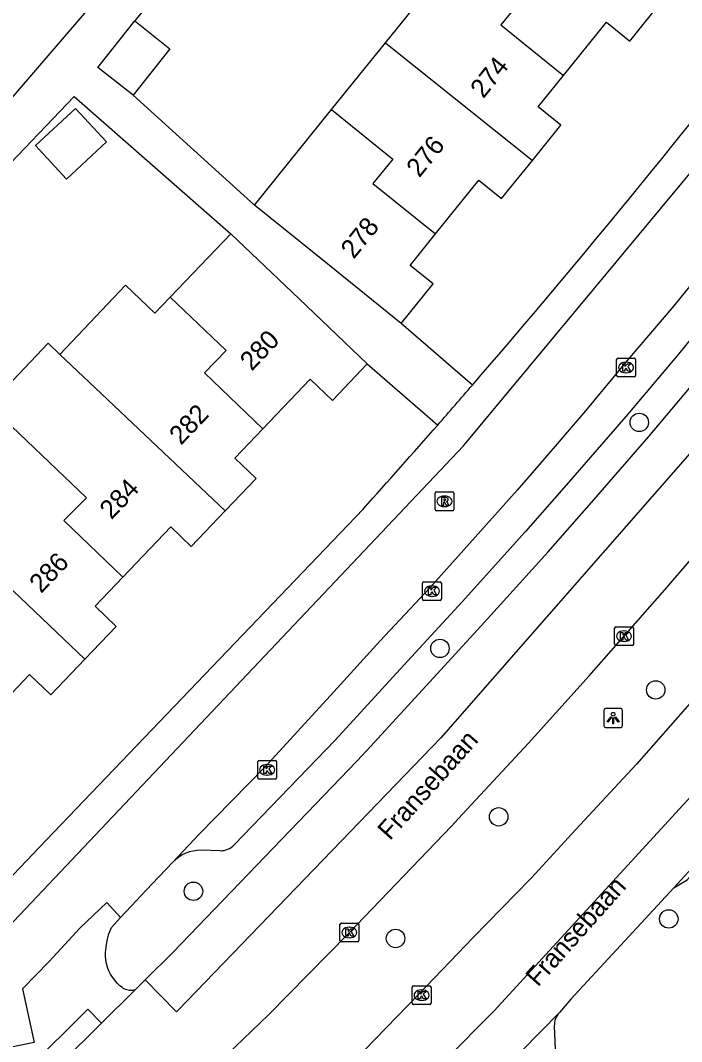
# Model space of a CAD drawing. Extents: x 158474 to 159560, y 388525 to 389605.
# Drawn here: x 158643.2 to 158678.3, y 388854.8 to 388909 of the extents above; entities that cross this region are included whole.
import ezdxf

# ---------------------------------------------------------------- set-up
doc = ezdxf.new("R2010")
doc.units = 0
for name, color, linetype in [('IMGEO_Boom', 7, 'Continuous'), ('IMGEO_Kolk', 7, 'Continuous'), ('IMGEO_Lichtpunt', 7, 'Continuous'), ('IMGEO_Openbare_ruimte_label', 7, 'Continuous'), ('IMGEO_Pand', 7, 'Continuous'), ('IMGEO_Pand_nummerreeks', 7, 'Continuous'), ('IMGEO_Parkeervlak_open', 7, 'Continuous'), ('IMGEO_Rijbaan_lokaal_gesloten', 7, 'Continuous'), ('IMGEO_Rijbaan_lokaal_open', 7, 'Continuous'), ('IMGEO_Rioolput', 7, 'Continuous'), ('IMGEO_Voetpad_open', 7, 'Continuous')]:
    doc.layers.add(name, color=color, linetype=linetype)

msp = doc.modelspace()

# ---------------------------------------------------------------- linework, layer by layer
at = {"layer": 'IMGEO_Boom'}
for centre in [(158676.07, 388887.651), (158665.49, 388875.653), (158676.946, 388873.453), (158668.608, 388866.715), (158652.407, 388862.762), (158677.641, 388861.294), (158663.133, 388860.257)]:
    msp.add_circle(centre, 0.489, dxfattribs=at)
at = {"layer": 'IMGEO_Kolk'}
for p, q in [((158674.871, 388890.139), (158674.871, 388890.991)), ((158674.946, 388891.065), (158675.798, 388891.065)), ((158675.359, 388890.845), (158675.384, 388890.845)), ((158675.872, 388890.991), (158675.872, 388890.139)), ((158675.382, 388890.285), (158675.357, 388890.285)), ((158675.798, 388890.065), (158674.946, 388890.065)), ((158664.568, 388878.271), (158664.568, 388879.123)), ((158664.643, 388879.197), (158665.495, 388879.197)), ((158665.056, 388878.977), (158665.081, 388878.977)), ((158665.569, 388879.123), (158665.569, 388878.271)), ((158665.079, 388878.417), (158665.054, 388878.417)), ((158665.495, 388878.197), (158664.643, 388878.197)), ((158674.762, 388875.875), (158674.762, 388876.727)), ((158674.837, 388876.801), (158675.689, 388876.801)), ((158675.763, 388876.727), (158675.763, 388875.875)), ((158675.25, 388876.581), (158675.275, 388876.581)), ((158675.689, 388875.801), (158674.837, 388875.801)), ((158675.273, 388876.021), (158675.248, 388876.021)), ((158655.819, 388868.783), (158655.819, 388869.635)), ((158655.894, 388869.709), (158656.746, 388869.709)), ((158656.82, 388869.635), (158656.82, 388868.783)), ((158656.307, 388869.489), (158656.332, 388869.489)), ((158656.746, 388868.709), (158655.894, 388868.709)), ((158656.33, 388868.929), (158656.305, 388868.929)), ((158660.181, 388860.15), (158660.181, 388861.002)), ((158660.256, 388861.076), (158661.108, 388861.076)), ((158661.182, 388861.002), (158661.182, 388860.15)), ((158660.669, 388860.856), (158660.694, 388860.856)), ((158661.108, 388860.076), (158660.256, 388860.076)), ((158660.692, 388860.296), (158660.667, 388860.296)), ((158664.016, 388856.825), (158664.016, 388857.677)), ((158664.091, 388857.751), (158664.943, 388857.751)), ((158665.017, 388857.677), (158665.017, 388856.825)), ((158664.504, 388857.531), (158664.529, 388857.531)), ((158664.943, 388856.751), (158664.091, 388856.751)), ((158664.527, 388856.971), (158664.502, 388856.971))]:
    msp.add_line(p, q, dxfattribs=at)
for points in [[(158674.871, 388890.139), (158674.871, 388890.991)], [(158674.946, 388891.065), (158675.798, 388891.065)], [(158675.192, 388890.765), (158675.315, 388890.765), (158675.315, 388890.614), (158675.445, 388890.765), (158675.609, 388890.765), (158675.463, 388890.614), (158675.616, 388890.365), (158675.464, 388890.365), (158675.379, 388890.529), (158675.315, 388890.462), (158675.315, 388890.365), (158675.192, 388890.365), (158675.192, 388890.765)], [(158675.872, 388890.991), (158675.872, 388890.139)], [(158675.798, 388890.065), (158674.946, 388890.065)], [(158664.568, 388878.271), (158664.568, 388879.123)], [(158664.643, 388879.197), (158665.495, 388879.197)], [(158664.889, 388878.897), (158665.012, 388878.897), (158665.012, 388878.746), (158665.142, 388878.897), (158665.306, 388878.897), (158665.16, 388878.746), (158665.313, 388878.497), (158665.161, 388878.497), (158665.076, 388878.661), (158665.012, 388878.594), (158665.012, 388878.497), (158664.889, 388878.497), (158664.889, 388878.897)], [(158665.569, 388879.123), (158665.569, 388878.271)], [(158665.495, 388878.197), (158664.643, 388878.197)], [(158674.762, 388875.875), (158674.762, 388876.727)], [(158674.837, 388876.801), (158675.689, 388876.801)], [(158675.763, 388876.727), (158675.763, 388875.875)], [(158675.083, 388876.501), (158675.206, 388876.501), (158675.206, 388876.35), (158675.336, 388876.501), (158675.5, 388876.501), (158675.354, 388876.35), (158675.507, 388876.101), (158675.355, 388876.101), (158675.27, 388876.265), (158675.206, 388876.198), (158675.206, 388876.101), (158675.083, 388876.101), (158675.083, 388876.501)], [(158675.689, 388875.801), (158674.837, 388875.801)], [(158655.819, 388868.783), (158655.819, 388869.635)], [(158655.894, 388869.709), (158656.746, 388869.709)], [(158656.82, 388869.635), (158656.82, 388868.783)], [(158656.14, 388869.409), (158656.263, 388869.409), (158656.263, 388869.258), (158656.393, 388869.409), (158656.557, 388869.409), (158656.411, 388869.258), (158656.564, 388869.009), (158656.412, 388869.009), (158656.327, 388869.173), (158656.263, 388869.106), (158656.263, 388869.009), (158656.14, 388869.009), (158656.14, 388869.409)], [(158656.746, 388868.709), (158655.894, 388868.709)], [(158660.181, 388860.15), (158660.181, 388861.002)], [(158660.256, 388861.076), (158661.108, 388861.076)], [(158661.182, 388861.002), (158661.182, 388860.15)], [(158660.502, 388860.776), (158660.625, 388860.776), (158660.625, 388860.625), (158660.755, 388860.776), (158660.919, 388860.776), (158660.773, 388860.625), (158660.926, 388860.376), (158660.774, 388860.376), (158660.689, 388860.54), (158660.625, 388860.473), (158660.625, 388860.376), (158660.502, 388860.376), (158660.502, 388860.776)], [(158661.108, 388860.076), (158660.256, 388860.076)], [(158664.016, 388856.825), (158664.016, 388857.677)], [(158664.091, 388857.751), (158664.943, 388857.751)], [(158665.017, 388857.677), (158665.017, 388856.825)], [(158664.337, 388857.451), (158664.46, 388857.451), (158664.46, 388857.3), (158664.59, 388857.451), (158664.754, 388857.451), (158664.608, 388857.3), (158664.761, 388857.051), (158664.609, 388857.051), (158664.524, 388857.215), (158664.46, 388857.148), (158664.46, 388857.051), (158664.337, 388857.051), (158664.337, 388857.451)], [(158664.943, 388856.751), (158664.091, 388856.751)]]:
    msp.add_lwpolyline(points, dxfattribs=at)
for centre, start, end in [((158674.948, 388890.989), 91.552, 178.448), ((158674.948, 388890.989), 91.552, 178.448), ((158675.796, 388890.989), 1.552, 88.448), ((158675.796, 388890.989), 1.552, 88.448), ((158674.948, 388890.141), 181.552, 268.448), ((158674.948, 388890.141), 181.552, 268.448), ((158675.796, 388890.141), 271.552, 358.448), ((158675.796, 388890.141), 271.552, 358.448), ((158664.645, 388879.121), 91.552, 178.448), ((158664.645, 388879.121), 91.552, 178.448), ((158665.493, 388879.121), 1.552, 88.448), ((158665.493, 388879.121), 1.552, 88.448), ((158664.645, 388878.273), 181.552, 268.448), ((158664.645, 388878.273), 181.552, 268.448), ((158665.493, 388878.273), 271.552, 358.448), ((158665.493, 388878.273), 271.552, 358.448), ((158674.839, 388876.725), 91.552, 178.448), ((158674.839, 388876.725), 91.552, 178.448), ((158675.687, 388876.725), 1.552, 88.448), ((158675.687, 388876.725), 1.552, 88.448), ((158674.839, 388875.877), 181.552, 268.448), ((158674.839, 388875.877), 181.552, 268.448), ((158675.687, 388875.877), 271.552, 358.448), ((158675.687, 388875.877), 271.552, 358.448), ((158655.896, 388869.633), 91.552, 178.448), ((158655.896, 388869.633), 91.552, 178.448), ((158656.744, 388869.633), 1.552, 88.448), ((158656.744, 388869.633), 1.552, 88.448), ((158655.896, 388868.785), 181.552, 268.448), ((158655.896, 388868.785), 181.552, 268.448), ((158656.744, 388868.785), 271.552, 358.448), ((158656.744, 388868.785), 271.552, 358.448), ((158660.258, 388861), 91.552, 178.448), ((158660.258, 388861), 91.552, 178.448), ((158661.106, 388861), 1.552, 88.448), ((158661.106, 388861), 1.552, 88.448), ((158660.258, 388860.152), 181.552, 268.448), ((158660.258, 388860.152), 181.552, 268.448), ((158661.106, 388860.152), 271.552, 358.448), ((158661.106, 388860.152), 271.552, 358.448), ((158664.093, 388857.675), 91.552, 178.448), ((158664.093, 388857.675), 91.552, 178.448), ((158664.941, 388857.675), 1.552, 88.448), ((158664.941, 388857.675), 1.552, 88.448), ((158664.093, 388856.827), 181.552, 268.448), ((158664.093, 388856.827), 181.552, 268.448), ((158664.941, 388856.827), 271.552, 358.448), ((158664.941, 388856.827), 271.552, 358.448)]:
    msp.add_arc(centre, 0.0765, start, end, dxfattribs=at)
for centre, major_axis, ratio, start_param, end_param in [((158675.358, 388890.565), (-0.387, 0.002), 0.722429, 4.712389, 7.853982), ((158675.383, 388890.565), (-0.39, 0.002), 0.717154, 1.570796, 4.712389), ((158665.055, 388878.697), (-0.387, 0.002), 0.722429, 4.712389, 7.853982), ((158665.08, 388878.697), (-0.39, 0.002), 0.717154, 1.570796, 4.712389), ((158675.249, 388876.301), (-0.387, 0.002), 0.722429, 4.712389, 7.853982), ((158675.274, 388876.301), (-0.39, 0.002), 0.717154, 1.570796, 4.712389), ((158656.306, 388869.209), (-0.387, 0.002), 0.722429, 4.712389, 7.853982), ((158656.331, 388869.209), (-0.39, 0.002), 0.717154, 1.570796, 4.712389), ((158660.668, 388860.576), (-0.387, 0.002), 0.722429, 4.712389, 7.853982), ((158660.693, 388860.576), (-0.39, 0.002), 0.717154, 1.570796, 4.712389), ((158664.503, 388857.251), (-0.387, 0.002), 0.722429, 4.712389, 7.853982), ((158664.528, 388857.251), (-0.39, 0.002), 0.717154, 1.570796, 4.712389)]:
    msp.add_ellipse(centre, major_axis=major_axis, ratio=ratio, start_param=start_param, end_param=end_param, dxfattribs=at)
at = {"layer": 'IMGEO_Lichtpunt'}
for p, q in [((158674.186, 388872.362), (158674.186, 388871.555)), ((158674.186, 388872.362), (158674.186, 388871.555)), ((158675.088, 388872.457), (158674.28, 388872.457)), ((158675.088, 388872.457), (158674.28, 388872.457)), ((158675.182, 388871.555), (158675.182, 388872.362)), ((158675.182, 388871.555), (158675.182, 388872.362)), ((158674.28, 388871.461), (158675.088, 388871.461)), ((158674.28, 388871.461), (158675.088, 388871.461))]:
    msp.add_line(p, q, dxfattribs=at)
for points in [[(158674.56, 388872.026), (158674.599, 388871.998), (158674.411, 388871.736), (158674.373, 388871.763), (158674.56, 388872.026)], [(158674.662, 388871.978), (158674.709, 388871.978), (158674.709, 388871.656), (158674.662, 388871.656), (158674.662, 388871.978)], [(158674.772, 388871.998), (158674.81, 388872.025), (158674.997, 388871.763), (158674.958, 388871.735), (158674.772, 388871.998)]]:
    msp.add_lwpolyline(points, dxfattribs=at)
msp.add_circle((158674.685, 388872.16), 0.0994, dxfattribs=at)
for centre, start, end in [((158674.28, 388872.362), 90, 180), ((158674.28, 388872.362), 90, 180), ((158675.088, 388872.362), 0, 90), ((158675.088, 388872.362), 0, 90), ((158674.28, 388871.555), 180, 270), ((158674.28, 388871.555), 180, 270), ((158675.088, 388871.555), 270, 0), ((158675.088, 388871.555), 270, 360)]:
    msp.add_arc(centre, 0.0946, start, end, dxfattribs=at)
at = {"layer": 'IMGEO_Pand'}
for points in [[(158662.596, 388907.797), (158666.523, 388912.669)], [(158666.523, 388912.669), (158669.78, 388910.05), (158668.73, 388908.75), (158672.051, 388906.068)], [(158672.051, 388906.068), (158674.328, 388908.894), (158675.571, 388907.892), (158677.223, 388909.942)], [(158649.202, 388905.02), (158647.337, 388906.496), (158649.288, 388908.962)], [(158649.288, 388908.962), (158651.153, 388907.486), (158649.202, 388905.02)], [(158659.741, 388904.253), (158662.596, 388907.797)], [(158662.596, 388907.797), (158670.402, 388901.56)], [(158670.402, 388901.56), (158671.908, 388903.429), (158670.706, 388904.398), (158672.051, 388906.068)], [(158645.66, 388900.564), (158644.013, 388902.345), (158646.148, 388904.318), (158647.794, 388902.538), (158645.66, 388900.564)], [(158655.653, 388899.181), (158659.741, 388904.253)], [(158659.741, 388904.253), (158662.99, 388901.63), (158661.93, 388900.34), (158665.263, 388897.66)], [(158665.263, 388897.66), (158667.556, 388900.505), (158668.766, 388899.53), (158670.402, 388901.56)], [(158663.438, 388892.908), (158659.544, 388896.045), (158655.653, 388899.181)], [(158651.174, 388894.299), (158654.39, 388897.669)], [(158654.39, 388897.669), (158658.018, 388894.207), (158661.636, 388890.756)], [(158663.438, 388892.908), (158665.126, 388895.004), (158663.911, 388895.983), (158665.263, 388897.66)], [(158645.314, 388891.262), (158648.801, 388894.93), (158650.361, 388893.447), (158651.174, 388894.299)], [(158651.174, 388894.299), (158654.15, 388891.46), (158653, 388890.28), (158656.094, 388887.315)], [(158641.567, 388888.565), (158644.692, 388891.853), (158645.314, 388891.262)], [(158645.314, 388891.262), (158646.868, 388889.785), (158654.082, 388882.949)], [(158656.094, 388887.315), (158658.605, 388889.947), (158659.787, 388888.819), (158661.636, 388890.756)], [(158641.567, 388888.565), (158646.72, 388883.65), (158645.52, 388882.44), (158648.663, 388879.445)], [(158654.082, 388882.949), (158655.727, 388884.672), (158654.599, 388885.748), (158656.094, 388887.315)], [(158646.641, 388875.09), (158639.407, 388881.965), (158637.246, 388884.018)], [(158648.663, 388879.445), (158651.199, 388882.103), (158652.286, 388881.066), (158654.082, 388882.949)], [(158646.641, 388875.09), (158648.296, 388876.825), (158647.18, 388877.89), (158648.663, 388879.445)], [(158641.182, 388871.642), (158643.694, 388874.274), (158644.829, 388873.191), (158646.641, 388875.09)]]:
    msp.add_lwpolyline(points, dxfattribs=at)
at = {"layer": 'IMGEO_Parkeervlak_open'}
for points in [[(158687.514, 388902.953), (158684.205, 388898.809), (158681.137, 388894.95), (158678.157, 388891.271), (158675.353, 388887.96), (158672.318, 388884.462), (158670.036, 388881.855), (158666.663, 388878.125), (158663.767, 388874.978), (158659.928, 388870.792), (158654.57, 388865.224)], [(158653.827, 388864.918), (158652.811, 388864.941)]]:
    msp.add_lwpolyline(points, dxfattribs=at)
for centre, radius, start, end in [((158652.813, 388862.825), 2.116, 90.0637, 135.2032), ((158653.851, 388865.915), 0.997, 268.6297, 316.1383)]:
    msp.add_arc(centre, radius, start, end, dxfattribs=at)
at = {"layer": 'IMGEO_Rijbaan_lokaal_gesloten'}
for points in [[(158816.351, 389056.585), (158812.361, 389054.997), (158810.132, 389053.866), (158806.876, 389051.639), (158804.716, 389049.617), (158803.379, 389048.28), (158800.43, 389044.703), (158777.642, 389014.753), (158751.605, 388980.623), (158732.013, 388954.68), (158705.771, 388920.107), (158682.617, 388890.402), (158665.532, 388870.907), (158651.596, 388856.454), (158651.514, 388856.372), (158649.845, 388858.063)], [(158654.546, 388838.744), (158652.694, 388840.633), (158668.364, 388856.424), (158683.318, 388872.712), (158697.002, 388889.186), (158717.328, 388915.448), (158737.178, 388941.567), (158754.114, 388963.852), (158766.121, 388979.65), (158778.301, 388995.677), (158798.192, 389021.851), (158809.433, 389036.528), (158811.777, 389039.288), (158814.069, 389041.449), (158818.297, 389044.22), (158821.97, 389045.718)], [(158649.845, 388858.063), (158651.306, 388859.511), (158661.102, 388869.689), (158661.805, 388870.456), (158664.954, 388873.888), (158667.853, 388877.039), (158671.24, 388880.784), (158673.533, 388883.403), (158676.576, 388886.911), (158679.398, 388890.243), (158682.394, 388893.941), (158685.595, 388897.967), (158688.786, 388901.962)], [(158697.521, 388895.303), (158694.933, 388891.894), (158692.302, 388888.672), (158689.133, 388884.755), (158686.992, 388882.254), (158684.423, 388879.16), (158681.461, 388875.79), (158679.017, 388873.024), (158675.923, 388869.515), (158672.68, 388866.029), (158670.348, 388863.48), (158670.301, 388863.43), (158667.252, 388860.316), (158664.378, 388857.295), (158661.495, 388854.32), (158659.8, 388852.588), (158653.743, 388846.575)], [(158654.172, 388854.084), (158656.398, 388856.202), (158660.635, 388860.529), (158666.105, 388866.215), (158666.464, 388866.603), (158670.19, 388870.631), (158673.414, 388874.206), (158677.431, 388878.763), (158680.221, 388882.024), (158685.824, 388888.819), (158689.146, 388892.868)], [(158677.905, 388862.94), (158674.867, 388859.654), (158672.448, 388857.038), (158671.833, 388856.333)], [(158649.845, 388858.063), (158649.292, 388857.515)], [(158649.292, 388857.515), (158647.531, 388855.77)], [(158654.775, 388838.972), (158671.833, 388856.333)], [(158647.531, 388855.77), (158641.069, 388849.367)]]:
    msp.add_lwpolyline(points, dxfattribs=at)
msp.add_arc((158023.278, 389459.392), 885.602, 317.662329, 318.263299, dxfattribs=at)
at = {"layer": 'IMGEO_Rijbaan_lokaal_open'}
for points in [[(158692.351, 388912.123), (158690.206, 388909.388), (158688.674, 388907.305), (158685.077, 388902.753), (158681.013, 388897.669), (158677.905, 388893.842), (158675.428, 388890.945), (158673.224, 388888.265), (158670.851, 388885.497), (158669.583, 388884.063), (158668.264, 388882.572), (158664.958, 388878.876), (158662.323, 388876.052), (158659.859, 388873.355), (158656.189, 388869.344), (158652.696, 388865.781), (158651.312, 388864.316)], [(158641.243, 388854.184), (158640.359, 388858.532), (158666.738, 388886.416), (158673.719, 388894.796), (158680.692, 388903.184)], [(158651.312, 388864.316), (158650.223, 388863.164), (158648.531, 388861.366)], [(158648.531, 388861.366), (158647.802, 388862.166), (158646.385, 388860.814), (158644.743, 388859.037), (158643.326, 388857.585), (158643.949, 388854.728), (158641.243, 388854.184)]]:
    msp.add_lwpolyline(points, dxfattribs=at)
at = {"layer": 'IMGEO_Rioolput'}
for p, q in [((158665.231, 388883.037), (158665.231, 388883.889)), ((158665.306, 388883.963), (158666.158, 388883.963)), ((158665.719, 388883.743), (158665.744, 388883.743)), ((158666.232, 388883.889), (158666.232, 388883.037)), ((158665.742, 388883.183), (158665.717, 388883.183)), ((158666.158, 388882.963), (158665.306, 388882.963))]:
    msp.add_line(p, q, dxfattribs=at)
for points in [[(158665.231, 388883.037), (158665.231, 388883.889)], [(158665.306, 388883.963), (158666.158, 388883.963)], [(158666.232, 388883.889), (158666.232, 388883.037)], [(158665.82, 388883.661), (158665.568, 388883.663), (158665.568, 388883.263)], [(158665.568, 388883.263), (158665.692, 388883.263), (158665.692, 388883.425), (158665.703, 388883.425)], [(158665.746, 388883.582), (158665.692, 388883.582), (158665.692, 388883.501)], [(158665.692, 388883.501), (158665.744, 388883.501)], [(158665.75, 388883.396), (158665.821, 388883.263), (158665.961, 388883.263), (158665.896, 388883.389)], [(158666.158, 388882.963), (158665.306, 388882.963)]]:
    msp.add_lwpolyline(points, dxfattribs=at)
for centre, radius, start, end in [((158665.308, 388883.887), 0.0765, 91.552, 178.448), ((158665.308, 388883.887), 0.0765, 91.552, 178.448), ((158666.156, 388883.887), 0.0765, 1.552, 88.448), ((158666.156, 388883.887), 0.0765, 1.552, 88.448), ((158665.702, 388883.372), 0.0533, 26.0293, 88.6989), ((158665.728, 388883.69), 0.19, 274.7715, 282.9687), ((158665.752, 388883.486), 0.0964, 77.0061, 93.1865), ((158665.766, 388883.543), 0.0378, 276.6634, 79.6772), ((158665.819, 388883.551), 0.109, 350.3612, 89.416), ((158665.817, 388883.551), 0.112, 277.5842, 350.9817), ((158665.801, 388883.336), 0.108, 29.5134, 73.7905), ((158665.308, 388883.039), 0.0765, 181.552, 268.448), ((158665.308, 388883.039), 0.0765, 181.552, 268.448), ((158666.156, 388883.039), 0.0765, 271.552, 358.448), ((158666.156, 388883.039), 0.0765, 271.552, 358.448)]:
    msp.add_arc(centre, radius, start, end, dxfattribs=at)
for centre, major_axis, ratio, start_param, end_param in [((158665.718, 388883.463), (-0.387, 0.002), 0.722429, 4.712389, 7.853982), ((158665.743, 388883.463), (-0.39, 0.002), 0.717154, 1.570796, 4.712389)]:
    msp.add_ellipse(centre, major_axis=major_axis, ratio=ratio, start_param=start_param, end_param=end_param, dxfattribs=at)
at = {"layer": 'IMGEO_Voetpad_open'}
for points in [[(158651.898, 388912.195), (158649.288, 388908.962)], [(158619.328, 388880.057), (158641.527, 388903.446), (158647.946, 388910.907)], [(158640.8, 388899.447), (158646.076, 388904.95), (158654.39, 388897.669)], [(158649.202, 388905.02), (158655.653, 388899.181)], [(158667.216, 388889.629), (158663.438, 388892.908)], [(158661.636, 388890.756), (158665.374, 388887.512)], [(158677.905, 388862.94), (158678.623, 388863.376), (158684.496, 388869.923), (158690.961, 388877.374), (158695.981, 388883.407), (158701.618, 388890.424), (158701.938, 388891.173)], [(158661.42, 388883.05), (158644.581, 388865.476), (158641.079, 388861.821), (158636.245, 388856.776)], [(158649.292, 388857.515), (158649.239, 388857.505), (158649.164, 388857.497), (158649.088, 388857.495), (158649.013, 388857.501), (158648.938, 388857.513), (158648.865, 388857.531), (158648.794, 388857.557), (158648.725, 388857.588), (158648.659, 388857.625), (158648.597, 388857.668), (158648.539, 388857.717), (158648.499, 388857.751), (158648.356, 388857.888), (158648.225, 388858.037), (158648.109, 388858.198), (158648.007, 388858.368), (158647.921, 388858.547), (158647.851, 388858.733), (158647.798, 388858.924), (158647.762, 388859.119), (158647.744, 388859.317), (158647.743, 388859.515), (158647.768, 388859.788), (158647.829, 388860.149), (158647.922, 388860.502), (158648.047, 388860.846), (158648.531, 388861.366)], [(158641.069, 388849.367), (158640.337, 388850.106), (158646.799, 388856.509), (158647.531, 388855.77)], [(158671.563, 388855.604), (158671.621, 388853.967)]]:
    msp.add_lwpolyline(points, dxfattribs=at)
for centre, radius, start, end in [((158308.503, 389199.866), 474.259, 319.14468, 321.90242), ((158368.478, 389147.701), 394.772, 318.76986, 319.17714), ((158316.591, 389192.603), 463.389, 318.08567, 318.82283), ((158672.585, 388855.64), 1.023, 137.3456, 182.0081)]:
    msp.add_arc(centre, radius, start, end, dxfattribs=at)

# ---------------------------------------------------------------- texts
at = {"layer": 'IMGEO_Openbare_ruimte_label'}
for rotation, p in [(48.2428, (158662.835, 388865.423)), (48.3236, (158670.695, 388857.647))]:
    msp.add_text('Fransebaan', height=1, rotation=rotation, dxfattribs=at).set_placement(p)
at = {"layer": 'IMGEO_Pand_nummerreeks'}
for s, rotation, p in [('274', 51.1449, (158667.796, 388904.804)), ('276', 51.1291, (158664.399, 388900.604)), ('278', 51.1291, (158660.918, 388896.285)), ('280', 46.3475, (158655.501, 388890.343)), ('282', 46.3475, (158651.746, 388886.408)), ('284', 46.35, (158648.053, 388882.455)), ('286', 46.35, (158644.319, 388878.541))]:
    msp.add_text(s, height=1, rotation=rotation, dxfattribs=at).set_placement(p)

doc.saveas('drawing.dxf')
